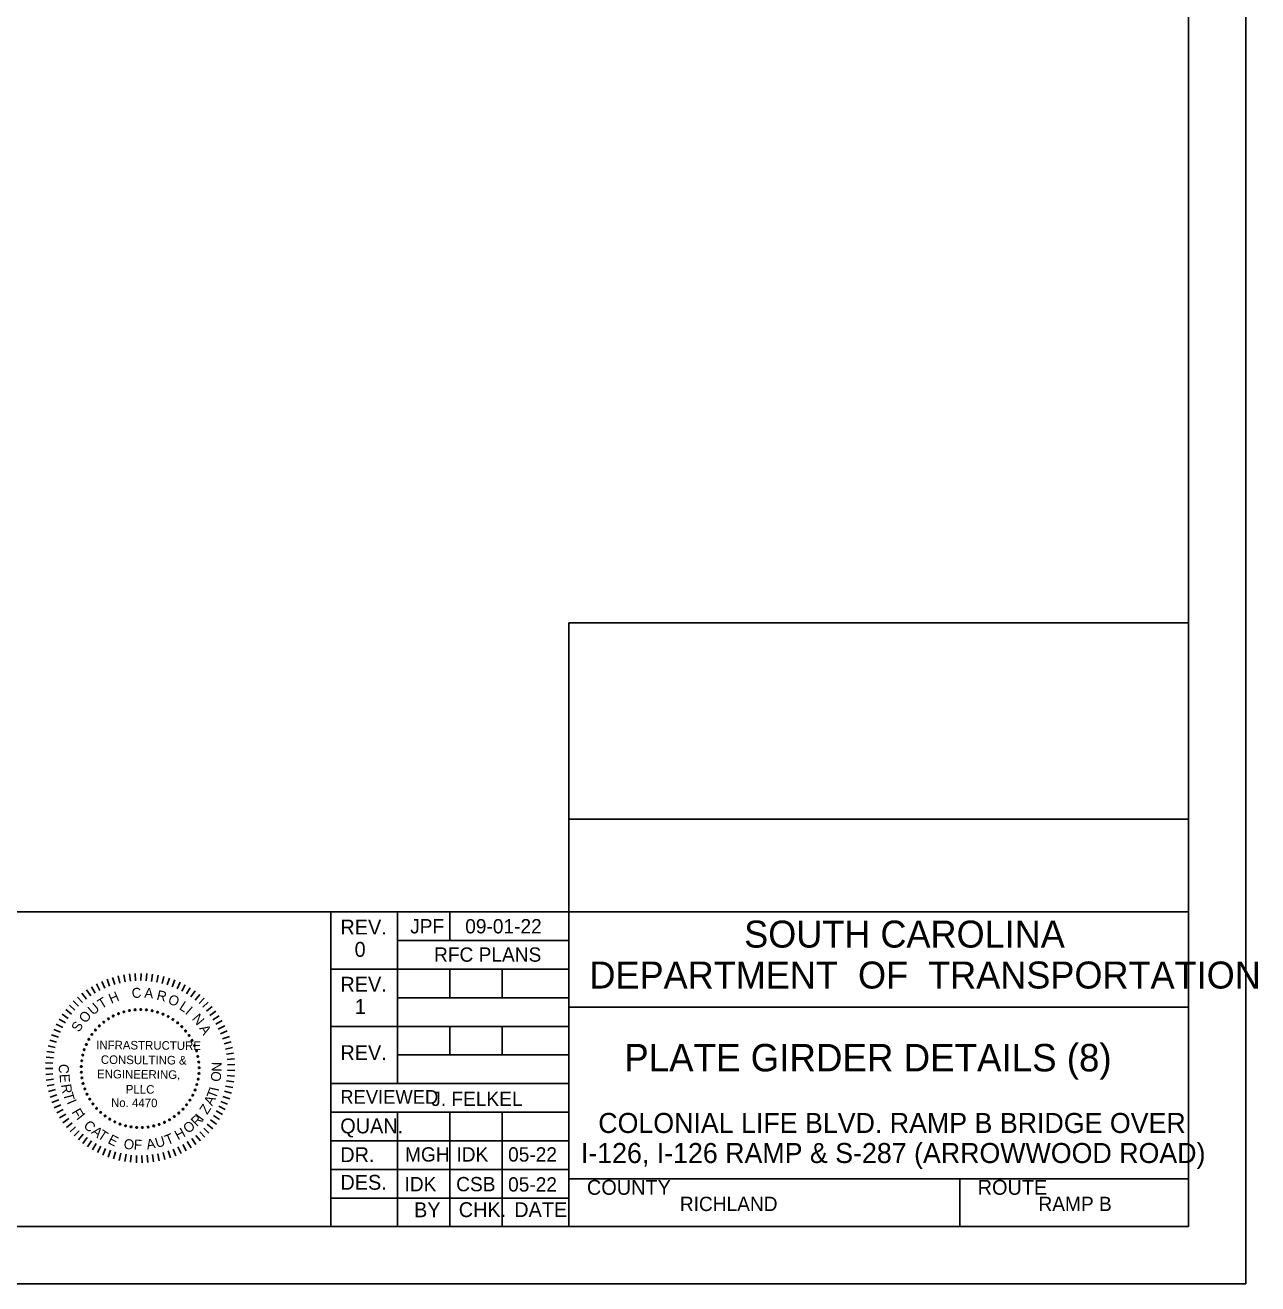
# Model space of a CAD drawing. Extents: x -305 to -161, y -187 to -99.
# Drawn here: x -203.87 to -160.75, y -187.49 to -143.49 of the extents above; entities that cross this region are included whole.
import ezdxf

# ---------------------------------------------------------------- set-up
doc = ezdxf.new("R2010")
doc.units = 0
for name, color, linetype in [('BR_BORDER LINES', 7, 'Continuous'), ('BR_TEXT', 7, 'Continuous'), ('Level 31', 7, 'Continuous')]:
    doc.layers.add(name, color=color, linetype=linetype)

msp = doc.modelspace()

# ---------------------------------------------------------------- linework, layer by layer
at = {"layer": 'BR_BORDER LINES'}
for p, q in [((-163.178, -185.489), (-163.178, -101.489)), ((-184.846, -185.489), (-184.846, -164.383)), ((-184.846, -164.383), (-163.178, -164.383)), ((-184.845, -171.242), (-163.178, -171.242)), ((-214.64, -174.489), (-193.18, -174.489)), ((-193.18, -185.489), (-193.18, -174.489)), ((-193.18, -174.489), (-163.178, -174.489)), ((-190.846, -174.489), (-190.846, -180.489)), ((-189.013, -175.489), (-189.013, -174.489)), ((-190.846, -175.489), (-184.846, -175.489)), ((-193.18, -176.489), (-184.846, -176.489)), ((-189.013, -177.489), (-189.013, -176.489)), ((-187.179, -177.489), (-187.179, -176.489)), ((-190.846, -177.489), (-184.846, -177.489)), ((-184.846, -177.822), (-184.846, -177.822)), ((-184.846, -177.823), (-163.178, -177.823)), ((-193.18, -178.489), (-184.846, -178.489)), ((-189.013, -179.489), (-189.013, -178.489)), ((-187.179, -179.489), (-187.179, -178.489)), ((-190.846, -179.489), (-184.846, -179.489)), ((-193.18, -180.489), (-184.846, -180.489)), ((-193.18, -181.489), (-184.846, -181.489)), ((-190.846, -181.489), (-190.846, -185.489)), ((-189.013, -181.489), (-189.013, -185.489)), ((-187.179, -181.489), (-187.179, -185.489)), ((-193.18, -182.489), (-184.846, -182.489)), ((-193.18, -183.489), (-184.846, -183.489)), ((-184.846, -183.823), (-163.178, -183.823)), ((-184.456, -183.823), (-163.178, -183.823)), ((-171.179, -185.489), (-171.179, -183.823)), ((-193.18, -184.489), (-184.846, -184.489)), ((-297.843, -185.489), (-163.178, -185.489))]:
    msp.add_line(p, q, dxfattribs=at)
at = {"layer": 'BR_TEXT'}
for p, q in [((-201.001, -176.844), (-200.912, -177.082)), ((-200.81, -176.779), (-200.735, -177.023)), ((-200.615, -176.726), (-200.555, -176.974)), ((-200.417, -176.685), (-200.373, -176.936)), ((-200.217, -176.656), (-200.188, -176.909)), ((-200.016, -176.64), (-200.002, -176.894)), ((-199.814, -176.636), (-199.816, -176.89)), ((-199.612, -176.644), (-199.63, -176.898)), ((-199.411, -176.664), (-199.444, -176.917)), ((-199.212, -176.697), (-199.26, -176.947)), ((-199.015, -176.741), (-199.079, -176.988)), ((-198.821, -176.798), (-198.9, -177.04)), ((-198.631, -176.866), (-198.724, -177.103)), ((-201.716, -177.215), (-201.572, -177.425)), ((-201.546, -177.106), (-201.415, -177.324)), ((-201.37, -177.007), (-201.252, -177.233)), ((-201.188, -176.92), (-201.084, -177.153)), ((-198.446, -176.946), (-198.553, -177.177)), ((-198.265, -177.037), (-198.387, -177.261)), ((-198.091, -177.139), (-198.226, -177.355)), ((-197.923, -177.251), (-198.071, -177.458)), ((-202.321, -177.748), (-202.13, -177.917)), ((-202.182, -177.601), (-202.002, -177.781)), ((-202.035, -177.463), (-201.866, -177.654)), ((-201.879, -177.334), (-201.723, -177.535)), ((-197.762, -177.373), (-197.922, -177.571)), ((-197.609, -177.505), (-197.781, -177.693)), ((-197.464, -177.646), (-197.647, -177.823)), ((-202.57, -178.065), (-202.36, -178.21)), ((-202.45, -177.903), (-202.25, -178.06)), ((-197.329, -177.795), (-197.522, -177.961)), ((-197.202, -177.952), (-197.405, -178.106)), ((-197.086, -178.117), (-197.298, -178.258)), ((-202.867, -178.593), (-202.634, -178.696)), ((-202.779, -178.411), (-202.553, -178.529)), ((-202.679, -178.235), (-202.461, -178.366)), ((-196.979, -178.289), (-197.199, -178.417)), ((-196.883, -178.467), (-197.111, -178.581)), ((-203.009, -178.97), (-202.766, -179.045)), ((-202.944, -178.779), (-202.705, -178.869)), ((-196.799, -178.65), (-197.033, -178.75)), ((-196.725, -178.838), (-196.965, -178.924)), ((-196.664, -179.03), (-196.908, -179.101)), ((-203.104, -179.363), (-202.853, -179.407)), ((-203.063, -179.165), (-202.815, -179.225)), ((-196.614, -179.226), (-196.862, -179.282)), ((-196.576, -179.424), (-196.827, -179.465)), ((-203.151, -179.764), (-202.897, -179.777)), ((-203.134, -179.562), (-202.881, -179.592)), ((-196.55, -179.625), (-196.804, -179.65)), ((-196.537, -179.826), (-196.791, -179.836)), ((-203.156, -179.965), (-202.901, -179.964)), ((-203.149, -180.167), (-202.895, -180.15)), ((-203.129, -180.368), (-202.877, -180.335)), ((-196.57, -180.43), (-196.822, -180.393)), ((-196.547, -180.23), (-196.8, -180.208)), ((-196.535, -180.028), (-196.79, -180.022)), ((-203.097, -180.568), (-202.847, -180.52)), ((-203.053, -180.765), (-202.807, -180.701)), ((-196.653, -180.825), (-196.899, -180.758)), ((-196.606, -180.629), (-196.855, -180.577)), ((-202.997, -180.959), (-202.755, -180.881)), ((-202.93, -181.149), (-202.693, -181.056)), ((-202.851, -181.335), (-202.62, -181.228)), ((-196.784, -181.207), (-197.02, -181.111)), ((-196.713, -181.018), (-196.954, -180.936)), ((-202.761, -181.516), (-202.536, -181.395)), ((-202.66, -181.69), (-202.443, -181.556)), ((-202.548, -181.859), (-202.34, -181.711)), ((-197.065, -181.743), (-197.279, -181.605)), ((-196.96, -181.57), (-197.182, -181.446)), ((-196.867, -181.392), (-197.096, -181.281)), ((-202.426, -182.02), (-202.228, -181.86)), ((-202.295, -182.173), (-202.107, -182.002)), ((-202.155, -182.319), (-201.977, -182.136)), ((-197.438, -182.219), (-197.623, -182.045)), ((-197.304, -182.068), (-197.5, -181.905)), ((-197.179, -181.91), (-197.385, -181.759)), ((-202.006, -182.455), (-201.84, -182.262)), ((-201.849, -182.582), (-201.695, -182.379)), ((-201.685, -182.699), (-201.543, -182.487)), ((-201.513, -182.806), (-201.385, -182.586)), ((-198.059, -182.734), (-198.196, -182.519)), ((-197.892, -182.62), (-198.042, -182.414)), ((-197.733, -182.495), (-197.895, -182.3)), ((-197.581, -182.362), (-197.756, -182.176)), ((-201.336, -182.903), (-201.221, -182.675)), ((-201.153, -182.988), (-201.053, -182.754)), ((-200.965, -183.062), (-200.879, -182.822)), ((-200.773, -183.125), (-200.702, -182.88)), ((-200.577, -183.175), (-200.521, -182.927)), ((-200.379, -183.214), (-200.338, -182.962)), ((-200.179, -183.24), (-200.154, -182.987)), ((-199.978, -183.254), (-199.968, -183)), ((-199.776, -183.256), (-199.781, -183.002)), ((-199.574, -183.246), (-199.595, -182.992)), ((-199.373, -183.223), (-199.41, -182.971)), ((-199.174, -183.188), (-199.226, -182.939)), ((-198.978, -183.142), (-199.045, -182.896)), ((-198.785, -183.083), (-198.867, -182.842)), ((-198.596, -183.012), (-198.692, -182.777)), ((-198.411, -182.93), (-198.522, -182.701)), ((-198.232, -182.837), (-198.356, -182.615))]:
    msp.add_line(p, q, dxfattribs=at)
for centre, start, end in [((-200.957, -178.226), 32.7576, 212.7576), ((-200.785, -178.127), 27.2191, 207.2191), ((-200.785, -178.127), 207.2191, 27.2191), ((-200.603, -178.045), 21.6807, 201.6807), ((-200.603, -178.045), 201.6807, 21.6807), ((-200.414, -177.98), 16.1422, 196.1422), ((-200.414, -177.98), 196.1422, 16.1422), ((-200.22, -177.935), 10.6038, 190.6038), ((-200.22, -177.935), 190.6038, 10.6038), ((-200.023, -177.908), 5.0653, 185.0653), ((-200.023, -177.908), 185.0653, 5.0653), ((-199.824, -177.9), 359.5268, 179.5268), ((-199.824, -177.9), 179.5268, 359.5268), ((-199.625, -177.912), 353.9884, 173.9884), ((-199.625, -177.912), 173.9884, 353.9884), ((-199.428, -177.943), 168.4499, 348.4499), ((-199.428, -177.943), 348.4499, 168.4499), ((-199.235, -177.992), 162.9114, 342.9114), ((-199.235, -177.992), 342.9114, 162.9114), ((-199.047, -178.06), 157.373, 337.373), ((-199.047, -178.06), 337.373, 157.373), ((-198.867, -178.146), 151.8345, 331.8345), ((-198.867, -178.146), 331.8345, 151.8345), ((-201.408, -178.617), 49.373, 229.373), ((-201.408, -178.617), 229.373, 49.373), ((-201.27, -178.472), 43.8345, 223.8345), ((-201.27, -178.472), 223.8345, 43.8345), ((-201.12, -178.341), 38.2961, 218.2961), ((-201.12, -178.341), 218.2961, 38.2961), ((-200.957, -178.226), 212.7576, 32.7576), ((-198.697, -178.249), 146.2961, 326.2961), ((-198.697, -178.249), 326.2961, 146.2961), ((-198.537, -178.368), 140.7576, 320.7576), ((-198.537, -178.368), 320.7576, 140.7576), ((-198.389, -178.502), 135.2191, 315.2191), ((-198.389, -178.502), 315.2191, 135.2191), ((-198.255, -178.649), 129.6807, 309.6807), ((-198.255, -178.649), 309.6807, 129.6807), ((-201.637, -178.942), 60.4499, 240.4499), ((-201.637, -178.942), 240.4499, 60.4499), ((-201.53, -178.774), 54.9114, 234.9114), ((-201.53, -178.774), 234.9114, 54.9114), ((-198.135, -178.809), 124.1422, 304.1422), ((-198.135, -178.809), 304.1422, 124.1422), ((-198.032, -178.979), 118.6038, 298.6038), ((-198.032, -178.979), 298.6038, 118.6038), ((-201.854, -179.497), 77.0653, 257.0653), ((-201.854, -179.497), 257.0653, 77.0653), ((-201.8, -179.305), 71.5268, 251.5268), ((-201.8, -179.305), 251.5268, 71.5268), ((-201.727, -179.12), 65.9884, 245.9884), ((-201.727, -179.12), 245.9884, 65.9884), ((-197.945, -179.159), 113.0653, 293.0653), ((-197.945, -179.159), 293.0653, 113.0653), ((-197.876, -179.346), 107.5268, 287.5268), ((-197.876, -179.346), 287.5268, 107.5268), ((-197.826, -179.538), 101.9884, 281.9884), ((-197.826, -179.538), 281.9884, 101.9884), ((-201.906, -179.892), 88.1422, 268.1422), ((-201.89, -179.693), 82.6038, 262.6038), ((-201.906, -179.892), 268.1422, 88.1422), ((-201.89, -179.693), 262.6038, 82.6038), ((-197.795, -179.735), 96.4499, 276.4499), ((-197.782, -179.934), 90.9114, 270.9114), ((-197.795, -179.735), 276.4499, 96.4499), ((-197.782, -179.934), 270.9114, 90.9114), ((-201.904, -180.091), 93.6807, 273.6807), ((-201.882, -180.289), 99.2191, 279.2191), ((-201.904, -180.091), 273.6807, 93.6807), ((-201.882, -180.289), 279.2191, 99.2191), ((-197.815, -180.331), 79.8345, 259.8345), ((-197.815, -180.331), 259.8345, 79.8345), ((-197.789, -180.133), 85.373, 265.373), ((-197.789, -180.133), 265.373, 85.373), ((-201.841, -180.484), 104.7576, 284.7576), ((-201.841, -180.484), 284.7576, 104.7576), ((-201.781, -180.675), 110.2961, 290.2961), ((-201.781, -180.675), 290.2961, 110.2961), ((-201.703, -180.858), 115.8345, 295.8345), ((-201.703, -180.858), 295.8345, 115.8345), ((-197.924, -180.714), 68.7576, 248.7576), ((-197.924, -180.714), 248.7576, 68.7576), ((-197.86, -180.525), 74.2961, 254.2961), ((-197.86, -180.525), 254.2961, 74.2961), ((-201.608, -181.033), 121.373, 301.373), ((-201.608, -181.033), 301.373, 121.373), ((-201.497, -181.199), 126.9114, 306.9114), ((-201.497, -181.199), 306.9114, 126.9114), ((-198.219, -181.232), 52.1422, 232.1422), ((-198.219, -181.232), 232.1422, 52.1422), ((-198.104, -181.069), 57.6807, 237.6807), ((-198.104, -181.069), 237.6807, 57.6807), ((-198.005, -180.896), 63.2191, 243.2191), ((-198.005, -180.896), 243.2191, 63.2191), ((-201.37, -181.352), 132.4499, 312.4499), ((-201.37, -181.352), 312.4499, 132.4499), ((-201.228, -181.493), 137.9884, 317.9884), ((-201.228, -181.493), 317.9884, 137.9884), ((-201.074, -181.619), 143.5268, 323.5268), ((-201.074, -181.619), 323.5268, 143.5268), ((-200.909, -181.73), 149.0653, 329.0653), ((-200.909, -181.73), 329.0653, 149.0653), ((-198.649, -181.644), 35.5268, 215.5268), ((-198.649, -181.644), 215.5268, 35.5268), ((-198.493, -181.521), 41.0653, 221.0653), ((-198.493, -181.521), 221.0653, 41.0653), ((-198.349, -181.383), 46.6038, 226.6038), ((-198.349, -181.383), 226.6038, 46.6038), ((-200.733, -181.825), 154.6038, 334.6038), ((-200.733, -181.825), 334.6038, 154.6038), ((-200.549, -181.902), 160.1422, 340.1422), ((-200.549, -181.902), 340.1422, 160.1422), ((-200.359, -181.961), 165.6807, 345.6807), ((-200.359, -181.961), 345.6807, 165.6807), ((-200.164, -182.001), 171.2191, 351.2191), ((-200.164, -182.001), 351.2191, 171.2191), ((-199.965, -182.022), 176.7576, 356.7576), ((-199.965, -182.022), 356.7576, 176.7576), ((-199.766, -182.024), 2.2961, 182.2961), ((-199.766, -182.024), 182.2961, 2.2961), ((-199.568, -182.007), 7.8345, 187.8345), ((-199.568, -182.007), 187.8345, 7.8345), ((-199.372, -181.971), 13.373, 193.373), ((-199.372, -181.971), 193.373, 13.373), ((-199.18, -181.916), 18.9114, 198.9114), ((-199.18, -181.916), 198.9114, 18.9114), ((-198.995, -181.842), 24.4499, 204.4499), ((-198.995, -181.842), 204.4499, 24.4499), ((-198.817, -181.752), 29.9884, 209.9884), ((-198.817, -181.752), 209.9884, 29.9884)]:
    msp.add_arc(centre, 0.028, start, end, dxfattribs=at)
at = {"layer": 'Level 31'}
msp.add_line((-174.011, -179.583), (-174.011, -179.583), dxfattribs=at)
msp.add_lwpolyline([(-305.176, -187.489), (-161.176, -187.489), (-161.176, -99.489), (-305.176, -99.489)], close=True, dxfattribs=at)

# ---------------------------------------------------------------- texts
at = {"layer": 'BR_TEXT'}
for s, height, p in [('REV.', 0.52, (-192.841, -175.277)), ('JPF', 0.5, (-190.4, -175.239)), ('09-01-22', 0.5, (-188.475, -175.239)), ('SOUTH CAROLINA', 0.94348, (-178.718, -175.735)), ('0', 0.52, (-192.345, -176.057)), ('RFC PLANS', 0.5, (-189.566, -176.229)), ('DEPARTMENT  OF  TRANSPORTATION', 0.94348, (-184.129, -177.166)), ('REV.', 0.52, (-192.841, -177.277)), ('1', 0.52, (-192.337, -178.057)), ('PLATE GIRDER DETAILS (8)', 0.96, (-182.913, -180.063)), ('REV.', 0.52, (-192.841, -179.667)), ('REVIEWED', 0.48, (-192.843, -181.195)), ('J. FELKEL', 0.5, (-189.664, -181.272)), ('QUAN.', 0.52, (-192.846, -182.229)), ('COLONIAL LIFE BLVD. RAMP B BRIDGE OVER', 0.7, (-183.82, -182.216)), ('I-126, I-126 RAMP & S-287 (ARROWWOOD ROAD) ', 0.7, (-184.429, -183.266)), ('DR.', 0.52, (-192.845, -183.235)), ('MGH', 0.5, (-190.58, -183.215)), ('IDK', 0.5, (-188.782, -183.215)), ('05-22', 0.5, (-186.975, -183.215)), ('DES.', 0.52, (-192.841, -184.2)), ('IDK', 0.5, (-190.598, -184.254)), ('CSB', 0.5, (-188.791, -184.254)), ('05-22', 0.5, (-186.975, -184.263)), ('COUNTY', 0.52, (-184.217, -184.376)), ('ROUTE', 0.52, (-170.55, -184.376)), ('BY', 0.52, (-190.265, -185.161)), ('CHK.', 0.52, (-188.701, -185.156)), ('DATE', 0.52, (-186.761, -185.156)), ('RICHLAND', 0.5, (-180.968, -184.944)), ('RAMP B', 0.5, (-168.424, -184.944))]:
    msp.add_text(s, height=height, dxfattribs=at).set_placement(p)
for s, height, rotation, p in [('H', 0.349, 22.7882, (-200.857, -177.704)), ('C', 0.349, 4.7281, (-200.126, -177.506)), ('A', 0.349, 355.6981, (-199.708, -177.486)), ('R', 0.349, 346.6681, (-199.291, -177.554)), ('U', 0.349, 40.8482, (-201.49, -178.119)), ('T', 0.349, 31.8182, (-201.196, -177.894)), ('O', 0.349, 337.638, (-198.9, -177.673)), ('L', 0.349, 327.108, (-198.504, -177.875)), ('O', 0.349, 49.8782, (-201.757, -178.403)), ('I', 0.349, 319.578, (-198.294, -178.026)), ('N', 0.349, 310.548, (-198.051, -178.23)), ('S', 0.349, 58.9083, (-201.979, -178.715)), ('A', 0.349, 301.5179, (-197.791, -178.559)), ('INFRASTRUCTURE', 0.29909, 359.5268, (-201.385, -179.286)), ('CONSULTING &', 0.29909, 359.5268, (-201.22, -179.8)), ('C', 0.349, 267.025, (-202.679, -179.795)), ('N', 0.349, 89.2085, (-196.993, -180.074)), ('E', 0.349, 273.025, (-202.662, -180.161)), ('ENGINEERING,', 0.29909, 359.5268, (-201.354, -180.302)), ('O', 0.349, 83.2085, (-197.038, -180.44)), ('R', 0.349, 279.025, (-202.61, -180.531)), ('T', 0.349, 285.025, (-202.541, -180.846)), ('PLLC', 0.2991, 359.5268, (-200.347, -180.836)), ('T', 0.349, 69.3954, (-197.203, -181.047)), ('I', 0.349, 77.9093, (-197.1, -180.777)), ('I', 0.349, 293.7713, (-202.422, -181.138)), ('No. 4470', 0.2991, 359.5268, (-200.865, -181.304)), ('Z', 0.349, 57.3954, (-197.501, -181.594)), ('A', 0.349, 63.3954, (-197.326, -181.288)), ('F', 0.349, 299.7713, (-202.257, -181.482)), ('I', 0.349, 308.5268, (-202.089, -181.698)), ('R', 0.349, 44.5268, (-197.863, -182.014)), ('I', 0.349, 52.3339, (-197.665, -181.825)), ('C', 0.349, 314.5268, (-201.851, -181.978)), ('A', 0.349, 320.5268, (-201.575, -182.213)), ('T', 0.349, 326.5268, (-201.357, -182.366)), ('H', 0.349, 28.5268, (-198.522, -182.478)), ('O', 0.349, 38.5268, (-198.169, -182.254)), ('E', 0.349, 332.5268, (-201.003, -182.558)), ('O', 0.349, 350.5268, (-200.442, -182.753)), ('F', 0.349, 356.5268, (-200.076, -182.79)), ('A', 0.349, 10.5268, (-199.597, -182.796)), ('U', 0.349, 16.5268, (-199.261, -182.742)), ('T', 0.349, 22.5268, (-198.894, -182.645))]:
    msp.add_text(s, height=height, rotation=rotation, dxfattribs=at).set_placement(p)

doc.saveas('drawing.dxf')
